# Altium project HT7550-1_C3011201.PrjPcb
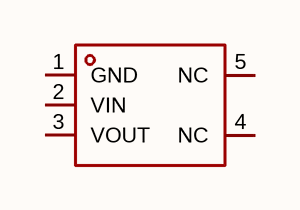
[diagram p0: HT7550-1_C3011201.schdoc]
1 sheet, 1 parts. Net scope: global (net labels, ports and power ports of the same name join across sheets).

## Sheet HT7550-1_C3011201.schdoc
size 127 x 101 mm

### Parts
U?  ht7550-1(sot23-5)  [SOT-23-5_L3.0-W1.7-P0.95-LS2.8-BL]  (value not drawn)

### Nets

Not connected (* = marked no-connect by the designer): U? 1(GND) 2(VIN) 3(VOUT) 4(NC) 5(NC)

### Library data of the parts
U? = ht7550-1(sot23-5): 输出极性:正极;工作电压:24V;输出电压:5V;输出电流:150mA;电源纹波抑制比(PSRR):68dB@(1kHz);输出类型:固定;; Manufacturer: TECH PUBLIC(台舟); Symbol: HT7550-1_C3011201; AddInBom: yes; ModelId: 0a2a1b8f50944f73965918ad6e5fe167; ModelName: SOT-23-5_L2.9-W1.6-H1.1-LS2.8-P0.95; ModelTransform: 118.60433,114.173,0,90,0,0,0.0005,0.0005,0; Output Configuration: 正极; Voltage - Supply: 24V; Output Voltage: 5V; Output Current: 150mA; Voltage Dropout: 420mV@(100mA); standby current: 1.5uA; Output Type: 固定; Number of Outputs: 1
